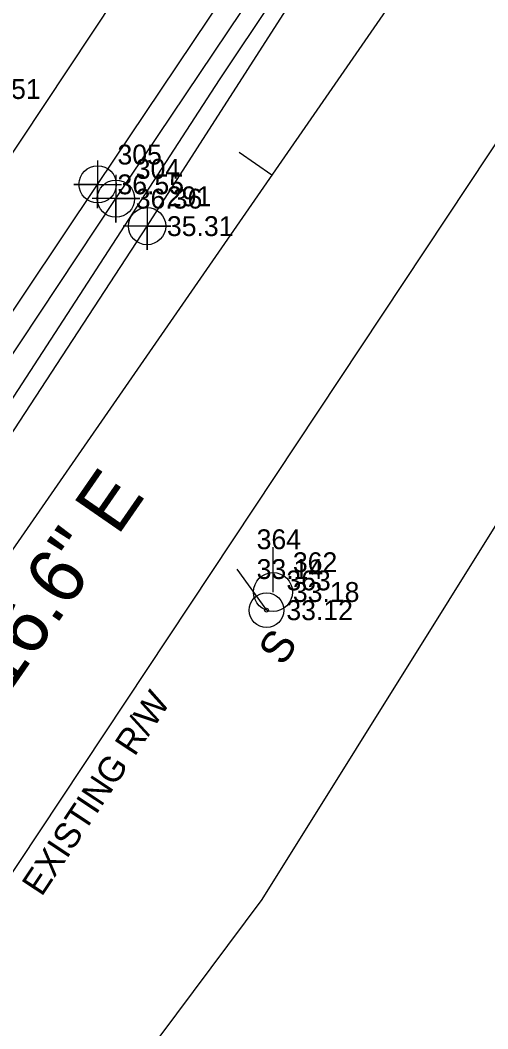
# Model space of a CAD drawing. Extents: x 2603627 to 2605187, y 896619 to 899063.
# Drawn here: x 2604728.2 to 2604787, y 898327.7 to 898454.7 of the extents above; entities that cross this region are included whole.
import ezdxf

# ---------------------------------------------------------------- set-up
doc = ezdxf.new("R2010")
doc.units = 0
for name, color, linetype in [('Exist Horizontal Alignment', 7, 'Continuous'), ('Exist Horizontal Baseline Alignment', 7, 'Continuous'), ('Exist Horizontal Baseline Alignment Direction Label', 7, 'Continuous'), ('Exist Horizontal Baseline Alignment Tick small', 7, 'Continuous'), ('Exist Other Culture Sign CELL', 7, 'Continuous'), ('Exist Other Culture Sign Cogo Elevation', 7, 'Continuous'), ('Exist Other Culture Sign Cogo Number', 7, 'Continuous'), ('Exist Other Culture Sign Text', 7, 'Continuous'), ('Exist Right of Way Line', 7, 'Continuous'), ('Exist Right of Way Line Text', 7, 'Continuous'), ('Exist Roads EOP', 7, 'Continuous'), ('Exist Roads EOP Cogo Elevation', 7, 'Continuous'), ('Exist Roads EOP Cogo Number', 7, 'Continuous'), ('Exist Roads EOP Cogo Point CELL', 7, 'Continuous'), ('Exist Roads EOT', 7, 'Continuous'), ('Exist Roads EOT Cogo Elevation', 7, 'Continuous'), ('Exist Roads EOT Cogo Number', 7, 'Continuous'), ('Exist Roads EOT Cogo Point CELL', 7, 'Continuous'), ('Exist Utilities Power Pole CELL', 7, 'Continuous'), ('Exist Utilities Power Pole Cogo Elevation', 7, 'Continuous'), ('Exist Utilities Power Pole Cogo Number', 7, 'Continuous'), ('Exist Utilities Telephone UG Cable SUE LOS C', 7, 'Continuous'), ('Exist Utilities Water UG Line SUE LOS B', 7, 'Continuous'), ('Exist Utilities Water UG Line SUE LOS B Cogo Elevation', 7, 'Continuous'), ('Exist Utilities Water UG Line SUE LOS B Cogo Number', 7, 'Continuous'), ('Exist Utilities Water UG Line SUE LOS B Cogo Point CELL', 7, 'Continuous'), ('Exist Vegetation Woods Line', 7, 'Continuous')]:
    doc.layers.add(name, color=color, linetype=linetype)

# ---------------------------------------------------------------- blocks, each defined once
blk = doc.blocks.new('EXIST UTILITIES WATER UG LINE SUE LOS B COGO POINT')
at = {"layer": 'Exist Utilities Water UG Line SUE LOS B Cogo Point CELL'}
blk.add_lwpolyline([(0, 0.06), (0, -0.06), (0, 0), (0.06, 0), (-0.06, 0)], dxfattribs=at)
blk.add_circle((0, 0), 0.0469, dxfattribs=at)
blk = doc.blocks.new('EXIST ROADS EOP COGO POINT')
at = {"layer": 'Exist Roads EOP Cogo Point CELL'}
blk.add_lwpolyline([(0, 0.06), (0, -0.06), (0, 0), (0.06, 0), (-0.06, 0)], dxfattribs=at)
blk.add_circle((0, 0), 0.0469, dxfattribs=at)
blk = doc.blocks.new('EXIST ROADS EOT COGO POINT')
at = {"layer": 'Exist Roads EOT Cogo Point CELL'}
blk.add_lwpolyline([(0, 0.06), (0, -0.06), (0, 0), (-0.06, 0), (0.06, 0)], dxfattribs=at)
blk.add_circle((0, 0), 0.0469, dxfattribs=at)
blk = doc.blocks.new('EXIST OTHER CULTURE SIGN')
at = {"layer": 'Exist Other Culture Sign CELL'}
for radius in [0.0436, 0.0048]:
    blk.add_circle((0, 0), radius, dxfattribs=at)

msp = doc.modelspace()

# ---------------------------------------------------------------- linework, layer by layer
at = {"layer": 'Exist Horizontal Alignment'}
msp.add_line((2604681.44, 898368.79), (2605041.11, 898911.74), dxfattribs=at)
at = {"layer": 'Exist Horizontal Baseline Alignment'}
msp.add_line((2604544.96, 898124.44), (2604793.6, 898483.9), dxfattribs=at)
at = {"layer": 'Exist Horizontal Baseline Alignment Tick small'}
msp.add_line((2604759.91, 898435.2), (2604755.8, 898438.05), dxfattribs=at)
at = {"layer": 'Exist Other Culture Sign CELL'}
msp.add_line((2604755.48, 898385.62), (2604759.22, 898380.44), dxfattribs=at)
at = {"layer": 'Exist Right of Way Line'}
msp.add_line((2604723.13, 898341.18), (2605082.79, 898884.13), dxfattribs=at)
at = {"layer": 'Exist Roads EOP'}
msp.add_lwpolyline([(2604713.86, 898392.44), (2604740.28, 898432.25), (2604768.45, 898474.26), (2604797.27, 898517.92), (2604823.93, 898558.47), (2604851.31, 898599.84), (2604878.52, 898641.09), (2604906.84, 898683.65), (2604934.68, 898725.71), (2604962.63, 898767.92), (2604989.32, 898808.49), (2605016.42, 898849.59), (2605045.34, 898893.33), (2605052.55, 898904.16)], dxfattribs=at)
at = {"layer": 'Exist Roads EOT'}
msp.add_lwpolyline([(2604598.04, 898223.4), (2604627.23, 898267.23), (2604654.64, 898308.57), (2604683.28, 898352.01), (2604711.27, 898394.14), (2604737.98, 898434.05), (2604766.04, 898475.94), (2604794.96, 898519.26), (2604821.61, 898559.82), (2604848.89, 898601.4), (2604876.12, 898642.73), (2604904.4, 898685.35), (2604932.33, 898727.23), (2604960.29, 898769.49), (2604987.32, 898810.19), (2605014.12, 898850.95), (2605043.08, 898894.89), (2605050.2, 898905.72)], dxfattribs=at)
at = {"layer": 'Exist Utilities Power Pole CELL'}
for q in [(2604760.04, 898388.36), (2604760.04, 898382.73)]:
    msp.add_line((2604760.04, 898382.73), q, dxfattribs=at)
msp.add_circle((2604760.04, 898382.73), 2.45, dxfattribs=at)
at = {"layer": 'Exist Utilities Telephone UG Cable SUE LOS C'}
for p, q in [((2604753.32, 898447.21), (2604850.74, 898593.69)), ((2604698.64, 898362.97), (2604753.32, 898447.21))]:
    msp.add_line(p, q, dxfattribs=at)
at = {"layer": 'Exist Utilities Water UG Line SUE LOS B'}
msp.add_lwpolyline([(2604590.41, 898183.07), (2604608.13, 898210.78), (2604631.33, 898247.72), (2604631.98, 898248.77), (2604637.93, 898260.9), (2604650.01, 898281.75), (2604670.13, 898312.66), (2604706.14, 898370.49), (2604744.2, 898428.79), (2604775.85, 898478.14), (2604817.62, 898541.22), (2604844.76, 898580.18), (2604876.2, 898627.22), (2604907.55, 898675.15), (2604931.69, 898711.47), (2604963.51, 898758.63), (2604991.08, 898800.9), (2605022.23, 898847.26), (2605044.13, 898880.13), (2605057.71, 898900.74)], dxfattribs=at)
at = {"layer": 'Exist Vegetation Woods Line'}
msp.add_lwpolyline([(2604653.24, 898142.95), (2604632.09, 898155.82), (2604674.87, 898231.68), (2604758.69, 898344.01), (2604864.62, 898513.8)], dxfattribs=at)

# ---------------------------------------------------------------- block references
at = {"layer": 'Exist Other Culture Sign CELL', "xscale": 50, "yscale": 50}
msp.add_blockref('EXIST OTHER CULTURE SIGN', (2604759.22, 898380.44), dxfattribs=at)
at = {"layer": 'Exist Roads EOP Cogo Point CELL', "xscale": 50, "yscale": 50}
msp.add_blockref('EXIST ROADS EOP COGO POINT', (2604740.28, 898432.25), dxfattribs=at)
at = {"layer": 'Exist Roads EOT Cogo Point CELL', "xscale": 50, "yscale": 50}
msp.add_blockref('EXIST ROADS EOT COGO POINT', (2604737.98, 898434.05), dxfattribs=at)
at = {"layer": 'Exist Utilities Water UG Line SUE LOS B Cogo Point CELL', "xscale": 50, "yscale": 50}
msp.add_blockref('EXIST UTILITIES WATER UG LINE SUE LOS B COGO POINT', (2604744.2, 898428.79), dxfattribs=at)

# ---------------------------------------------------------------- texts
at = {"layer": 'Exist Horizontal Baseline Alignment Direction Label'}
msp.add_text('N 34%%d 40\' 16.6" E', height=7, rotation=55.3287, dxfattribs=at).set_placement((2604703.48, 898336.18))
at = {"layer": 'Exist Other Culture Sign Cogo Elevation'}
for s, p in [('33.14', (2604757.98, 898384.37)), ('33.12', (2604761.72, 898379.19))]:
    msp.add_text(s, height=2.5, dxfattribs=at).set_placement(p)
at = {"layer": 'Exist Other Culture Sign Cogo Number'}
for s, p in [('364', (2604757.98, 898388.12)), ('363', (2604761.72, 898382.94))]:
    msp.add_text(s, height=2.5, dxfattribs=at).set_placement(p)
at = {"layer": 'Exist Other Culture Sign Text'}
msp.add_text('S', height=4, rotation=56.4094, dxfattribs=at).set_placement((2604761.29, 898373.27))
at = {"layer": 'Exist Right of Way Line Text'}
msp.add_text('EXISTING R/W', height=3.2, rotation=56.4785, dxfattribs=at).set_placement((2604730.94, 898344.28))
at = {"layer": 'Exist Roads EOP Cogo Elevation'}
msp.add_text('36.36', height=2.5, dxfattribs=at).set_placement((2604742.78, 898431))
at = {"layer": 'Exist Roads EOP Cogo Number'}
msp.add_text('304', height=2.5, dxfattribs=at).set_placement((2604742.78, 898434.75))
at = {"layer": 'Exist Roads EOT Cogo Elevation'}
for s, p in [('36.51', (2604722.45, 898444.8)), ('36.55', (2604740.48, 898432.8))]:
    msp.add_text(s, height=2.5, dxfattribs=at).set_placement(p)
at = {"layer": 'Exist Roads EOT Cogo Number'}
msp.add_text('305', height=2.5, dxfattribs=at).set_placement((2604740.48, 898436.55))
at = {"layer": 'Exist Utilities Power Pole Cogo Elevation'}
msp.add_text('33.18', height=2.5, dxfattribs=at).set_placement((2604762.54, 898381.48))
at = {"layer": 'Exist Utilities Power Pole Cogo Number'}
msp.add_text('362', height=2.5, dxfattribs=at).set_placement((2604762.54, 898385.23))
at = {"layer": 'Exist Utilities Water UG Line SUE LOS B Cogo Elevation'}
msp.add_text('35.31', height=2.5, dxfattribs=at).set_placement((2604746.7, 898427.54))
at = {"layer": 'Exist Utilities Water UG Line SUE LOS B Cogo Number'}
msp.add_text('291', height=2.5, dxfattribs=at).set_placement((2604746.7, 898431.29))

doc.saveas('drawing.dxf')
